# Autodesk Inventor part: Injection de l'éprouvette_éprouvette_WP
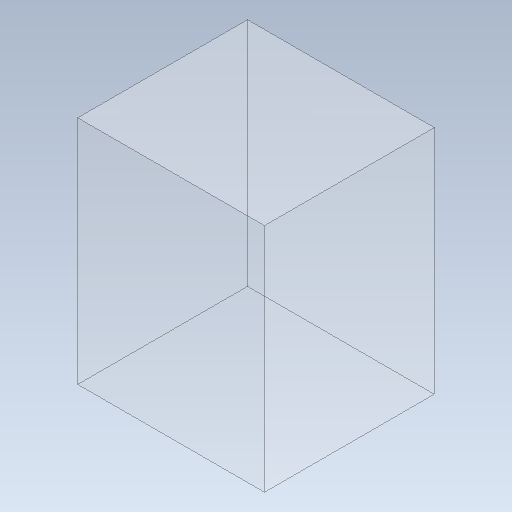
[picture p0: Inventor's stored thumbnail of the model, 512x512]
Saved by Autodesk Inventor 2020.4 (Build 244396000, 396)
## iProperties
Created: 2021-10
Part Number: Injection de l'éprouvette_éprouvette_WP
Material: Générique
Document SubType Name: Modeling
Designer: mel
Density: 1 g/cm^3
Appearance: Par défaut
Xmin: -27,500 mm
Ymin: -34,000 mm
Zmin: -25,000 mm
Xmax: 27,500 mm
Ymax: 34,000 mm
Zmax: 25,000 mm
d7: -25,000 mm
d8: 27,500 mm
d9: 27,500 mm
d10: 34,000 mm
d11: 34,000 mm
d12: 50,000 mm
d13: 0,00 deg
Author: mel
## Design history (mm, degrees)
sketch "Esquisse2"
  geometry: L1 (-27.5, 34)-(27.5, 34); L2 (27.5, 34)-(27.5, -34); L3 (27.5, -34)-(-27.5, -34); L4 (-27.5, -34)-(-27.5, 34); 1 further point
  constraints: 8 end point, 2 parallel, 1 horizontal, 1 perpendicular, 1 other
  dimensions: "d8" = 27.5 distance from line of L4 point (0, 0) (= -Xmin); "d9" = 27.5 distance from line of L2 point (0, 0) (= Xmax); "d10" = 34 distance from line of L3 point (0, 0) (= -Ymin); "d11" = 34 distance from line of L1 point (0, 0) (= Ymax)
extrude "Extrusion2" join sketch "Esquisse2" distance "d12" = 50 (= Zmax - Zmin); taper "d13" = 0 deg
node "Solide2"
other parameters: "Xmin" = -27.5 [user parameter; used in 1 equation term], "Ymin" = -34 [user parameter; used in 1 equation term], "Zmin" = -25 [user parameter; used in 1 equation term], "Xmax" = 27.5 [user parameter; used in 1 equation term], "Ymax" = 34 [user parameter; used in 1 equation term], "Zmax" = 25 [user parameter; used in 1 equation term], "d7" = -25
